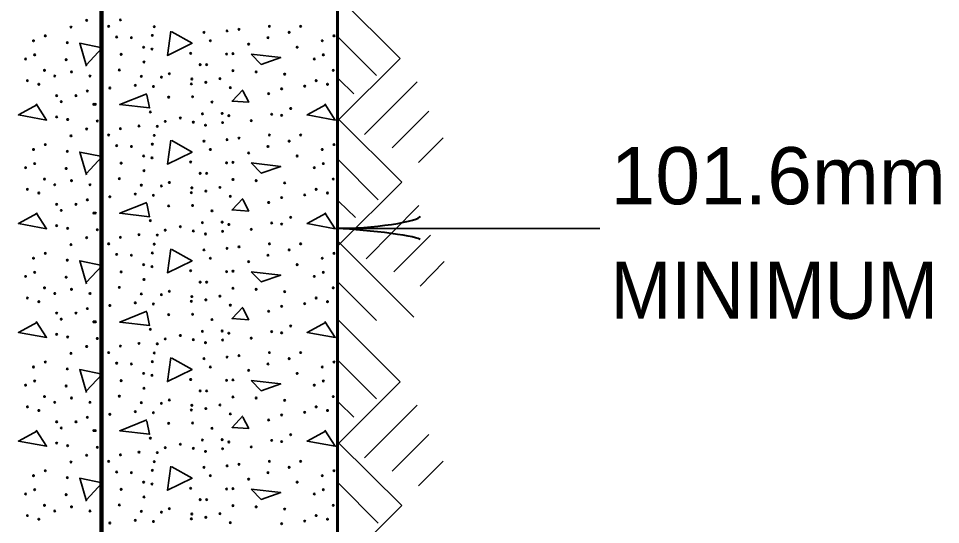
# Model space of a CAD drawing. Extents: x 442 to 1297, y -1132 to -588.
# Drawn here: x 662.37 to 701.01, y -935.08 to -913.86 of the extents above; entities that cross this region are included whole.
import ezdxf

# ---------------------------------------------------------------- set-up
doc = ezdxf.new("R2010")
doc.units = 0
doc.header["$LTSCALE"] = 0.96
doc.layers.add('1', color=7, linetype='Continuous', lineweight=35)

msp = doc.modelspace()

# ---------------------------------------------------------------- linework, layer by layer
at = {"layer": '1', "lineweight": 53}
for p, q in [((675.7476, -980.7675), (675.7476, -886.6076)), ((675.7476, -886.6076), (675.7476, -980.8522))]:
    msp.add_line(p, q, dxfattribs=at)
at = {"layer": '1', "lineweight": 106}
msp.add_line((665.8476, -971.1675), (665.8476, -893.8481), dxfattribs=at)
at = {"layer": '1'}
for p, q in [((675.7956, -912.9675), (678.3636, -915.5355)), ((675.7956, -914.6715), (677.3796, -916.2555)), ((675.7956, -918.1035), (678.3636, -915.5355)), ((675.7956, -916.3995), (676.4196, -917.0235)), ((676.8756, -918.7275), (679.0836, -916.5195)), ((678.0276, -919.2795), (679.5636, -917.7435)), ((675.7956, -918.1035), (678.4356, -920.7195)), ((679.1316, -919.9035), (680.1636, -918.8715)), ((675.7956, -919.8075), (677.4516, -921.4635)), ((675.7956, -923.3595), (678.4356, -920.7195)), ((675.7956, -921.5355), (676.4916, -922.2075)), ((676.9476, -923.9355), (679.1556, -921.7035)), ((675.7476, -922.6705), (686.7285, -922.6705)), ((678.0996, -924.4875), (679.6356, -922.9515)), ((675.7956, -923.2395), (678.9396, -926.3835)), ((679.2036, -925.0875), (680.2116, -924.0555)), ((675.7956, -924.9435), (677.3796, -926.5275)), ((675.7956, -926.5275), (678.3636, -929.0955)), ((675.7956, -928.2315), (677.3796, -929.8155)), ((675.7956, -931.6635), (678.3636, -929.0955)), ((675.7956, -929.9595), (676.4196, -930.5835)), ((676.8756, -932.2875), (679.0836, -930.0795)), ((678.0276, -932.8395), (679.5636, -931.3035)), ((675.7956, -931.6635), (678.4356, -934.2795)), ((679.1316, -933.4635), (680.1636, -932.4315)), ((675.7956, -933.3675), (677.4516, -935.0235)), ((675.7956, -936.9195), (678.4356, -934.2795))]:
    msp.add_line(p, q, dxfattribs=at)
for points in [[(668.8058, -914.4227), (669.6458, -914.9027), (668.6138, -915.4067), (668.7578, -914.3987)], [(665.2298, -915.8627), (664.9418, -914.9027), (665.8778, -915.0947), (665.2058, -915.8147)], [(667.7498, -917.0147), (666.6218, -917.4707), (667.8698, -917.6147), (667.7498, -917.0627)], [(671.7818, -916.8467), (671.3258, -917.3267), (672.0218, -917.3747), (671.7818, -916.8947)], [(663.1658, -917.4707), (662.3738, -917.9027), (663.5498, -918.1187), (663.1178, -917.4467)], [(675.2618, -917.4707), (674.4698, -917.9027), (675.6458, -918.1187), (675.2138, -917.4467)], [(668.8058, -918.9827), (669.6458, -919.4627), (668.6138, -919.9667), (668.7578, -918.9587)], [(665.2298, -920.4227), (664.9418, -919.4627), (665.8778, -919.6547), (665.2058, -920.3747)], [(671.7818, -921.4067), (671.3258, -921.8867), (672.0218, -921.9347), (671.7818, -921.4547)], [(667.7498, -921.5747), (666.6218, -922.0307), (667.8698, -922.1747), (667.7498, -921.6227)], [(663.1658, -922.0307), (662.3738, -922.4627), (663.5498, -922.6787), (663.1178, -922.0067)], [(675.2618, -922.0307), (674.4698, -922.4627), (675.6458, -922.6787), (675.2138, -922.0067)], [(668.8058, -923.5427), (669.6458, -924.0227), (668.6138, -924.5267), (668.7578, -923.5187)], [(665.2298, -924.9827), (664.9418, -924.0227), (665.8778, -924.2147), (665.2058, -924.9347)], [(671.7818, -925.9667), (671.3258, -926.4467), (672.0218, -926.4947), (671.7818, -926.0147)], [(667.7498, -926.1347), (666.6218, -926.5907), (667.8698, -926.7347), (667.7498, -926.1827)], [(663.1658, -926.5907), (662.3738, -927.0227), (663.5498, -927.2387), (663.1178, -926.5667)], [(675.2618, -926.5907), (674.4698, -927.0227), (675.6458, -927.2387), (675.2138, -926.5667)], [(668.8058, -928.1027), (669.6458, -928.5827), (668.6138, -929.0867), (668.7578, -928.0787)], [(665.2298, -929.5427), (664.9418, -928.5827), (665.8778, -928.7747), (665.2058, -929.4947)], [(667.7498, -930.6947), (666.6218, -931.1507), (667.8698, -931.2947), (667.7498, -930.7427)], [(671.7818, -930.5267), (671.3258, -931.0067), (672.0218, -931.0547), (671.7818, -930.5747)], [(663.1658, -931.1507), (662.3738, -931.5827), (663.5498, -931.7987), (663.1178, -931.1267)], [(675.2618, -931.1507), (674.4698, -931.5827), (675.6458, -931.7987), (675.2138, -931.1267)], [(668.8058, -932.6627), (669.6458, -933.1427), (668.6138, -933.6467), (668.7578, -932.6387)], [(665.2298, -934.1027), (664.9418, -933.1427), (665.8778, -933.3347), (665.2058, -934.0547)]]:
    msp.add_lwpolyline(points, dxfattribs=at)
for points in [[(672.1178, -915.3587), (673.3658, -915.5027), (672.5498, -915.7907)], [(672.1178, -919.9187), (673.3658, -920.0627), (672.5498, -920.3507)], [(672.1178, -924.4787), (673.3658, -924.6227), (672.5498, -924.9107)], [(672.1178, -929.0387), (673.3658, -929.1827), (672.5498, -929.4707)], [(672.1178, -933.5987), (673.3658, -933.7427), (672.5498, -934.0307)]]:
    msp.add_lwpolyline(points, close=True, dxfattribs=at)
for centre in [(665.2317, -913.9362), (666.6472, -913.9203), (664.5797, -914.2226), (666.1542, -914.1907), (668.0626, -914.2066), (670.1459, -914.4452), (671.1161, -914.3816), (671.6182, -914.318), (672.8905, -914.1907), (673.7176, -914.4452), (674.1947, -914.1907), (663.0052, -914.7953), (663.4982, -914.5885), (664.4206, -914.8748), (666.4881, -914.6362), (667.1083, -914.668), (667.9831, -914.5725), (670.4164, -914.7953), (672.827, -914.668), (675.1012, -914.7953), (675.5942, -914.5885), (667.6173, -915.0658), (667.9672, -915.1453), (672.0159, -914.9385), (674.0515, -915.0658), (662.6712, -915.5589), (663.053, -915.3839), (664.3729, -915.5907), (666.6789, -915.368), (669.5893, -915.3203), (671.0925, -915.3548), (671.3638, -915.3361), (674.7672, -915.5589), (675.149, -915.3839), (663.4664, -916.0362), (666.5995, -916.0202), (667.6332, -915.6862), (669.987, -915.7976), (670.2573, -915.7976), (675.5624, -916.0362), (663.8958, -916.2749), (664.5956, -916.0998), (665.3749, -916.2749), (667.5219, -916.2907), (668.3648, -916.3225), (668.6988, -916.1794), (669.6371, -916.4021), (670.8139, -916.3861), (671.3638, -916.0521), (672.334, -916.0998), (673.5268, -916.1952), (662.7508, -916.4657), (663.2278, -916.619), (666.2018, -916.7781), (667.2674, -916.6667), (668.0308, -916.7145), (669.6212, -916.6031), (670.2255, -916.5395), (671.2525, -916.7621), (673.3996, -916.8099), (674.3697, -916.6985), (674.8468, -916.4657), (675.3238, -916.619), (663.9753, -917.0962), (664.7864, -917.0962), (665.2636, -916.9053), (668.6669, -917.1599), (669.6689, -917.144), (672.8588, -917.0167), (664.1662, -917.3508), (665.5339, -917.4621), (665.5975, -917.4621), (670.48, -917.3666), (667.9035, -917.7803), (670.0823, -917.8598), (670.9094, -917.8439), (671.1889, -917.9394), (672.986, -917.8758), (673.3996, -917.9235), (673.7812, -917.6371), (663.9754, -917.9872), (664.4365, -918.0984), (665.6771, -918.1621), (667.4265, -918.3689), (668.5238, -918.1781), (669.1599, -918.0348), (669.7007, -918.2098), (670.2097, -918.3371), (670.9252, -918.2257), (672.1272, -918.1462), (665.2317, -918.4962), (666.1542, -918.7507), (666.6472, -918.4803), (668.1898, -918.3848), (672.8905, -918.7507), (674.1947, -918.7507), (664.5797, -918.7826), (667.9831, -919.1325), (668.0626, -918.7666), (670.1459, -919.0052), (671.1161, -918.9416), (671.6182, -918.878), (673.7176, -919.0052), (663.0052, -919.3553), (663.4982, -919.1485), (664.4206, -919.4348), (666.4881, -919.1962), (667.1083, -919.228), (670.4164, -919.3553), (672.0159, -919.4985), (672.827, -919.228), (675.1012, -919.3553), (675.5942, -919.1485), (667.6173, -919.6258), (667.9672, -919.7053), (669.5893, -919.8803), (671.0925, -919.9148), (671.3638, -919.8961), (674.0515, -919.6258), (662.6712, -920.1189), (663.053, -919.9439), (664.3729, -920.1507), (666.6789, -919.928), (667.6332, -920.2462), (674.7672, -920.1189), (675.149, -919.9439), (663.4664, -920.5962), (664.5956, -920.6598), (666.5995, -920.5802), (669.987, -920.3576), (670.2573, -920.3576), (671.3638, -920.6121), (672.334, -920.6598), (675.5624, -920.5962), (662.7508, -921.0257), (663.8958, -920.8349), (665.3749, -920.8349), (667.5219, -920.8507), (668.3648, -920.8825), (668.6988, -920.7394), (669.6371, -920.9621), (670.8139, -920.9461), (673.5268, -920.7552), (674.8468, -921.0257), (663.2278, -921.179), (666.2018, -921.3381), (667.2674, -921.2267), (668.0308, -921.2745), (669.6212, -921.1631), (670.2255, -921.0995), (671.2525, -921.3221), (673.3996, -921.3699), (674.3697, -921.2585), (675.3238, -921.179), (663.9753, -921.6562), (664.7864, -921.6562), (665.2636, -921.4653), (668.6669, -921.7199), (669.6689, -921.704), (672.8588, -921.5767), (664.1662, -921.9108), (665.5339, -922.0221), (665.5975, -922.0221), (670.48, -921.9266), (673.7812, -922.1971), (663.9754, -922.5472), (667.9035, -922.3403), (669.1599, -922.5948), (670.0823, -922.4198), (670.9094, -922.4039), (671.1889, -922.4994), (672.986, -922.4358), (673.3996, -922.4835), (664.4365, -922.6584), (665.6771, -922.7221), (667.4265, -922.9289), (668.1898, -922.9448), (668.5238, -922.7381), (669.7007, -922.7698), (670.2097, -922.8971), (670.9252, -922.7857), (672.1272, -922.7062), (664.5797, -923.3426), (665.2317, -923.0562), (666.1542, -923.3107), (666.6472, -923.0403), (668.0626, -923.3266), (672.8905, -923.3107), (674.1947, -923.3107), (663.4982, -923.7085), (666.4881, -923.7562), (667.9831, -923.6925), (670.1459, -923.5652), (671.1161, -923.5016), (671.6182, -923.438), (673.7176, -923.5652), (675.5942, -923.7085), (663.0052, -923.9153), (664.4206, -923.9948), (667.1083, -923.788), (670.4164, -923.9153), (672.0159, -924.0585), (672.827, -923.788), (675.1012, -923.9153), (663.053, -924.5039), (666.6789, -924.488), (667.6173, -924.1858), (667.9672, -924.2653), (669.5893, -924.4403), (671.0925, -924.4748), (671.3638, -924.4561), (674.0515, -924.1858), (675.149, -924.5039), (662.6712, -924.6789), (664.3729, -924.7107), (667.6332, -924.8062), (669.987, -924.9176), (670.2573, -924.9176), (674.7672, -924.6789), (663.4664, -925.1562), (664.5956, -925.2198), (666.5995, -925.1402), (668.6988, -925.2994), (671.3638, -925.1721), (672.334, -925.2198), (673.5268, -925.3152), (675.5624, -925.1562), (662.7508, -925.5857), (663.8958, -925.3949), (665.3749, -925.3949), (667.5219, -925.4107), (668.3648, -925.4425), (669.6371, -925.5221), (670.2255, -925.6595), (670.8139, -925.5061), (674.8468, -925.5857), (663.2278, -925.739), (665.2636, -926.0253), (666.2018, -925.8981), (667.2674, -925.7867), (668.0308, -925.8345), (669.6212, -925.7231), (671.2525, -925.8821), (673.3996, -925.9299), (674.3697, -925.8185), (675.3238, -925.739), (663.9753, -926.2162), (664.1662, -926.4708), (664.7864, -926.2162), (668.6669, -926.2799), (669.6689, -926.264), (672.8588, -926.1367), (665.5339, -926.5821), (665.5975, -926.5821), (670.48, -926.4866), (673.7812, -926.7571), (663.9754, -927.1072), (664.4365, -927.2184), (667.9035, -926.9003), (669.1599, -927.1548), (670.0823, -926.9798), (670.9094, -926.9639), (671.1889, -927.0594), (672.986, -926.9958), (673.3996, -927.0435), (665.2317, -927.6162), (665.6771, -927.2821), (666.6472, -927.6003), (667.4265, -927.4889), (668.1898, -927.5048), (668.5238, -927.2981), (669.7007, -927.3298), (670.2097, -927.4571), (670.9252, -927.3457), (672.1272, -927.2662), (664.5797, -927.9026), (666.1542, -927.8707), (668.0626, -927.8866), (671.6182, -927.998), (672.8905, -927.8707), (674.1947, -927.8707), (663.4982, -928.2685), (666.4881, -928.3162), (667.1083, -928.348), (667.9831, -928.2525), (670.1459, -928.1252), (671.1161, -928.0616), (672.827, -928.348), (673.7176, -928.1252), (675.5942, -928.2685), (663.0052, -928.4753), (664.4206, -928.5548), (667.6173, -928.7458), (670.4164, -928.4753), (672.0159, -928.6185), (674.0515, -928.7458), (675.1012, -928.4753), (663.053, -929.0639), (666.6789, -929.048), (667.9672, -928.8253), (669.5893, -929.0003), (671.0925, -929.0348), (671.3638, -929.0161), (675.149, -929.0639), (662.6712, -929.2389), (664.3729, -929.2707), (667.6332, -929.3662), (669.987, -929.4776), (670.2573, -929.4776), (674.7672, -929.2389), (663.4664, -929.7162), (663.8958, -929.9549), (664.5956, -929.7798), (665.3749, -929.9549), (666.5995, -929.7002), (668.6988, -929.8594), (671.3638, -929.7321), (672.334, -929.7798), (673.5268, -929.8752), (675.5624, -929.7162), (662.7508, -930.1457), (663.2278, -930.299), (667.5219, -929.9707), (668.3648, -930.0025), (669.6212, -930.2831), (669.6371, -930.0821), (670.2255, -930.2195), (670.8139, -930.0661), (674.8468, -930.1457), (675.3238, -930.299), (665.2636, -930.5853), (666.2018, -930.4581), (667.2674, -930.3467), (668.0308, -930.3945), (671.2525, -930.4421), (672.8588, -930.6967), (673.3996, -930.4899), (674.3697, -930.3785), (663.9753, -930.7762), (664.1662, -931.0308), (664.7864, -930.7762), (668.6669, -930.8399), (669.6689, -930.824), (670.48, -931.0466), (665.5339, -931.1421), (665.5975, -931.1421), (667.9035, -931.4603), (673.7812, -931.3171), (663.9754, -931.6672), (664.4365, -931.7784), (665.6771, -931.8421), (668.5238, -931.8581), (669.1599, -931.7148), (669.7007, -931.8898), (670.0823, -931.5398), (670.9094, -931.5239), (671.1889, -931.6194), (672.1272, -931.8262), (672.986, -931.5558), (673.3996, -931.6035), (665.2317, -932.1762), (666.6472, -932.1603), (667.4265, -932.0489), (668.1898, -932.0648), (670.2097, -932.0171), (670.9252, -931.9057), (664.5797, -932.4626), (666.1542, -932.4307), (668.0626, -932.4466), (671.1161, -932.6216), (671.6182, -932.558), (672.8905, -932.4307), (674.1947, -932.4307), (663.0052, -933.0353), (663.4982, -932.8285), (666.4881, -932.8762), (667.1083, -932.908), (667.9831, -932.8125), (670.1459, -932.6852), (670.4164, -933.0353), (672.827, -932.908), (673.7176, -932.6852), (675.1012, -933.0353), (675.5942, -932.8285), (664.4206, -933.1148), (667.6173, -933.3058), (667.9672, -933.3853), (672.0159, -933.1785), (674.0515, -933.3058), (662.6712, -933.7989), (663.053, -933.6239), (666.6789, -933.608), (669.5893, -933.5603), (671.0925, -933.5948), (671.3638, -933.5761), (674.7672, -933.7989), (675.149, -933.6239), (664.3729, -933.8307), (667.6332, -933.9262), (669.987, -934.0376), (670.2573, -934.0376), (663.4664, -934.2762), (663.8958, -934.5149), (664.5956, -934.3398), (665.3749, -934.5149), (666.5995, -934.2602), (667.5219, -934.5307), (668.3648, -934.5625), (668.6988, -934.4194), (671.3638, -934.2921), (672.334, -934.3398), (673.5268, -934.4352), (675.5624, -934.2762), (662.7508, -934.7057), (663.2278, -934.859), (667.2674, -934.9067), (668.0308, -934.9545), (669.6212, -934.8431), (669.6371, -934.6421), (670.2255, -934.7795), (670.8139, -934.6261), (674.3697, -934.9385), (674.8468, -934.7057), (675.3238, -934.859), (666.2018, -935.0181), (671.2525, -935.0021), (673.3996, -935.0499)]:
    msp.add_circle(centre, 0.0318, dxfattribs=at)
at = {"layer": '1', "lineweight": 40}
for centre, major_axis, ratio, start_param, end_param in [((677.057, -922.3389), (-2.1428, -0.1874), 0.122415, 0.8963533, 3.1415927), ((677.0922, -922.9244), (2.1077, -0.2108), 0.07063, 6.2823074, 8.5597026)]:
    msp.add_ellipse(centre, major_axis=major_axis, ratio=ratio, start_param=start_param, end_param=end_param, dxfattribs=at)

# ---------------------------------------------------------------- texts
at = {"layer": '1'}
for s, width, p in [('101.6mm', 1.05, (687.1833, -921.6546)), ('MINIMUM', 0.95, (687.1833, -926.4546))]:
    msp.add_text(s, height=2.4, dxfattribs=dict(at, width=width)).set_placement(p)

doc.saveas('drawing.dxf')
